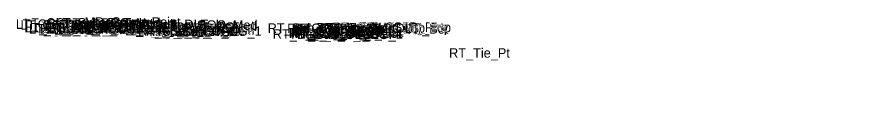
# Model space of a CAD drawing. Extents: x 0 to 4229, y -1 to 9523.
# Drawn here: x 2122.8 to 2300, y 0 to 16.8 of the extents above; entities that cross this region are included whole.
import ezdxf

# ---------------------------------------------------------------- set-up
doc = ezdxf.new("R2010")
doc.units = 0
doc.layers.add('Default', color=7, linetype='Continuous')

msp = doc.modelspace()

# ---------------------------------------------------------------- texts
at = {"layer": 'Default'}
for s, height, p in [('LT_CG_Top_Face_Med', 2, (2122.62, 14.23)), ('LT_CG_Top_Gut_Med', 2, (2123.6, 14.06)), ('LT_CG_Top_BOC_Med', 2, (2124.4, 14.48)), ('LT_PV1_PGL', 2, (2130.28, 14.08)), ('LT_Sub_DLT_In', 2, (2131.03, 14.52)), ('MD_Crown Point', 2, (2137.07, 14.68)), ('RT_CG_Top_BOC_Med', 2, (2144.34, 14.04)), ('RT_Sub_DLT_In', 2, (2146.79, 14.18)), ('LT_CG_Bot_BOC_Med', 2, (2124.44, 13.47)), ('LT_CG_Bot_IE_Med', 2, (2124.56, 13.5)), ('LT_Sub_IEOT_CG_1', 2, (2125.37, 13.25)), ('LT_Sub_OEEOP', 2, (2127.71, 13.2)), ('LT_PV2_OEEOP', 2, (2127.81, 13.83)), ('LT_PV3_OEEOP', 2, (2127.81, 13.58)), ('LT_Sub_IEEOP', 2, (2128.36, 13.2)), ('LT_PV2_IEEOP', 2, (2128.45, 13.83)), ('LT_CG1_Shelf_In', 2, (2128.68, 13.46)), ('LT_Sub_PGL', 2, (2129.62, 13.2)), ('LT_PV2_PGL', 2, (2129.71, 13.83)), ('LT_Sub_IEOP', 2, (2131.52, 13.2)), ('RT_CG_Top_Face_Med', 2, (2144.07, 13.79)), ('RT_CG_Bot_BOC_Med', 2, (2144.37, 13.06)), ('RT_CG_Top_Gut_Med', 2, (2145.05, 13.62)), ('RT_CG_Bot_IE_Med', 2, (2147.52, 13.02)), ('RT_CG1_Shelf_In', 2, (2147.62, 13.07)), ('RT_Sub_IEOT_CG_1', 2, (2148.32, 12.77)), ('RT_Sub_IEOP', 2, (2149.95, 12.82)), ('RT_Sub_OEEOP', 2, (2150.67, 12.73)), ('RT_PV2_OEEOP', 2, (2150.76, 13.36)), ('RT_PV3_OEEOP', 2, (2150.76, 13.11)), ('RT_Sub_IEEOP', 2, (2151.31, 12.73)), ('RT_PV2_IEEOP', 2, (2151.41, 13.36)), ('RT_Sub_PGL', 2, (2152.57, 12.73)), ('RT_PV2_PGL', 2, (2152.67, 13.36)), ('RT_PV1_PGL', 2, (2153.23, 13.61)), ('RT_Sub_Trench_Out_DLT', 2, (2175.6, 13.39)), ('RT_Sub_OEOT_CG_1', 2, (2176.67, 12.14)), ('RT_CG_Top_Face', 2, (2179.71, 13.35)), ('RT_CG1_Shelf_Out', 2, (2180, 12.33)), ('RT_CG_Bot_IE', 2, (2180.37, 12.39)), ('RT_Sub_OEOT', 2, (2180.53, 12.1)), ('RT_PV2_OEOT', 2, (2180.63, 12.72)), ('RT_PV3_OEOT', 2, (2180.63, 12.47)), ('RT_CG_Top_Gut', 2, (2180.69, 12.85)), ('RT_PV1_OEOT', 2, (2181.19, 12.97)), ('RT_CG_Top_BOC', 2, (2181.24, 13.35)), ('RT_CG_Bot_BOC', 2, (2181.27, 12.34)), ('RT_Sub_OEOP', 2, (2183.82, 12.07)), ('RT_SDWK_In_Top', 2, (2185.81, 13.46)), ('RT_SDWK_In_Bot', 2, (2185.84, 13.13)), ('RT_SDWK_Out_Top', 2, (2189.19, 13.56)), ('RT_SDWK_Out_Bot', 2, (2189.22, 13.23)), ('RT_CSLP_Pnt', 2, (2195.13, 13.59)), ('RT_Tie_Pt', 2, (2213.75, 8.14)), ('-', 0.0001, (2300, 0))]:
    msp.add_text(s, height=height, dxfattribs=at).set_placement(p)

doc.saveas('drawing.dxf')
